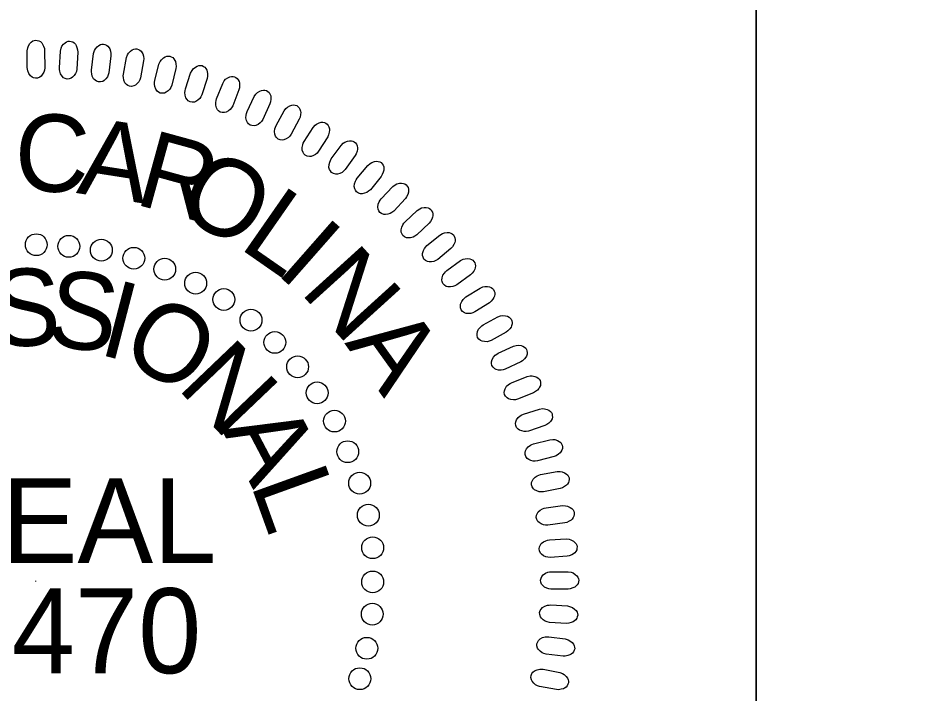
# Model space of a CAD drawing. Extents: x 505237 to 506921, y 424821 to 425921.
# Drawn here: x 506749.5 to 506815.5, y 425800.2 to 425849.7 of the extents above; entities that cross this region are included whole.
import ezdxf

# ---------------------------------------------------------------- set-up
doc = ezdxf.new("R2010")
doc.units = 0
doc.layers.add('Prop Horizontal Alignment Station Label', color=7, linetype='Continuous')
doc.layers.add('Sheet PE Seal Cell', color=7, linetype='Continuous')

msp = doc.modelspace()

# ---------------------------------------------------------------- linework, layer by layer
at = {"layer": 'Prop Horizontal Alignment Station Label'}
msp.add_line((506803.715, 425870.619), (506803.715, 425758.169), dxfattribs=at)
for points in [[(506703.665, 425870.619), (506803.715, 425870.619), (506803.715, 425758.119), (506703.665, 425758.119)], [(506803.715, 425870.619), (506903.715, 425870.619), (506903.715, 425758.119), (506803.715, 425758.119)]]:
    msp.add_lwpolyline(points, close=True, dxfattribs=at)
at = {"layer": 'Sheet PE Seal Cell'}
msp.add_line((506750.802, 425808.43), (506750.802, 425808.383), dxfattribs=at)
for points in [[(506750.198, 425846.115), (506750.198, 425847.342), (506750.236, 425847.561), (506750.289, 425847.702), (506750.4, 425847.871), (506750.498, 425847.981), (506750.61, 425848.061), (506750.714, 425848.1), (506750.827, 425848.12), (506750.938, 425848.1), (506751.058, 425848.071), (506751.163, 425848.011), (506751.267, 425847.911), (506751.327, 425847.831), (506751.394, 425847.681), (506751.455, 425847.502), (506751.477, 425847.342), (506751.484, 425846.086), (506751.462, 425845.916), (506751.417, 425845.777), (506751.327, 425845.617), (506751.215, 425845.477), (506751.118, 425845.398), (506750.961, 425845.338), (506750.812, 425845.318), (506750.662, 425845.358), (506750.558, 425845.407), (506750.43, 425845.507), (506750.311, 425845.677), (506750.243, 425845.856), (506750.214, 425845.986)], [(506752.558, 425846.09), (506752.635, 425847.314), (506752.685, 425847.531), (506752.747, 425847.667), (506752.869, 425847.829), (506752.973, 425847.932), (506753.09, 425848.005), (506753.197, 425848.038), (506753.31, 425848.051), (506753.421, 425848.024), (506753.538, 425847.987), (506753.639, 425847.92), (506753.737, 425847.815), (506753.792, 425847.731), (506753.85, 425847.578), (506753.898, 425847.395), (506753.911, 425847.234), (506753.839, 425845.979), (506753.806, 425845.811), (506753.752, 425845.675), (506753.653, 425845.522), (506753.532, 425845.389), (506753.43, 425845.315), (506753.27, 425845.266), (506753.119, 425845.255), (506752.973, 425845.304), (506752.871, 425845.361), (506752.751, 425845.468), (506752.642, 425845.645), (506752.586, 425845.828), (506752.565, 425845.96)], [(506754.92, 425845.916), (506755.074, 425847.133), (506755.138, 425847.346), (506755.208, 425847.477), (506755.34, 425847.632), (506755.451, 425847.729), (506755.572, 425847.793), (506755.68, 425847.82), (506755.794, 425847.826), (506755.903, 425847.791), (506756.018, 425847.747), (506756.114, 425847.675), (506756.205, 425847.562), (506756.255, 425847.476), (506756.304, 425847.319), (506756.34, 425847.133), (506756.342, 425846.972), (506756.192, 425845.725), (506756.148, 425845.559), (506756.087, 425845.427), (506755.978, 425845.279), (506755.849, 425845.155), (506755.743, 425845.088), (506755.579, 425845.048), (506755.428, 425845.047), (506755.285, 425845.105), (506755.187, 425845.168), (506755.073, 425845.283), (506754.976, 425845.466), (506754.932, 425845.653), (506754.919, 425845.785)], [(506757.26, 425845.63), (506757.49, 425846.835), (506757.567, 425847.043), (506757.645, 425847.17), (506757.787, 425847.316), (506757.903, 425847.405), (506758.028, 425847.463), (506758.138, 425847.482), (506758.252, 425847.481), (506758.358, 425847.441), (506758.47, 425847.389), (506758.562, 425847.31), (506758.646, 425847.193), (506758.69, 425847.104), (506758.728, 425846.944), (506758.753, 425846.756), (506758.745, 425846.595), (506758.517, 425845.359), (506758.463, 425845.197), (506758.393, 425845.068), (506758.275, 425844.928), (506758.138, 425844.812), (506758.028, 425844.752), (506757.863, 425844.723), (506757.712, 425844.731), (506757.573, 425844.798), (506757.48, 425844.867), (506757.374, 425844.989), (506757.288, 425845.178), (506757.255, 425845.366), (506757.25, 425845.5)], [(506759.565, 425845.157), (506759.87, 425846.345), (506759.961, 425846.548), (506760.046, 425846.671), (506760.197, 425846.807), (506760.318, 425846.889), (506760.447, 425846.938), (506760.558, 425846.951), (506760.672, 425846.943), (506760.775, 425846.895), (506760.884, 425846.836), (506760.97, 425846.753), (506761.046, 425846.63), (506761.085, 425846.538), (506761.113, 425846.376), (506761.126, 425846.187), (506761.109, 425846.027), (506760.803, 425844.808), (506760.739, 425844.65), (506760.66, 425844.526), (506760.534, 425844.393), (506760.391, 425844.286), (506760.277, 425844.233), (506760.11, 425844.214), (506759.96, 425844.232), (506759.826, 425844.308), (506759.737, 425844.382), (506759.638, 425844.51), (506759.564, 425844.704), (506759.544, 425844.895), (506759.547, 425845.027)], [(506761.815, 425844.535), (506762.194, 425845.702), (506762.298, 425845.9), (506762.391, 425846.016), (506762.55, 425846.143), (506762.676, 425846.217), (506762.807, 425846.258), (506762.919, 425846.264), (506763.032, 425846.248), (506763.132, 425846.194), (506763.237, 425846.129), (506763.318, 425846.039), (506763.386, 425845.913), (506763.419, 425845.818), (506763.437, 425845.655), (506763.438, 425845.466), (506763.41, 425845.307), (506763.029, 425844.11), (506762.955, 425843.955), (506762.869, 425843.836), (506762.735, 425843.712), (506762.585, 425843.614), (506762.468, 425843.568), (506762.3, 425843.56), (506762.151, 425843.588), (506762.022, 425843.671), (506761.938, 425843.751), (506761.848, 425843.885), (506761.786, 425844.083), (506761.778, 425844.275), (506761.79, 425844.408)], [(506764.099, 425843.801), (506764.55, 425844.942), (506764.666, 425845.132), (506764.766, 425845.243), (506764.933, 425845.359), (506765.064, 425845.425), (506765.197, 425845.458), (506765.309, 425845.457), (506765.421, 425845.434), (506765.517, 425845.374), (506765.618, 425845.302), (506765.693, 425845.208), (506765.754, 425845.077), (506765.78, 425844.981), (506765.787, 425844.817), (506765.777, 425844.628), (506765.739, 425844.471), (506765.283, 425843.3), (506765.2, 425843.151), (506765.107, 425843.037), (506764.965, 425842.923), (506764.809, 425842.833), (506764.69, 425842.795), (506764.521, 425842.798), (506764.375, 425842.834), (506764.251, 425842.926), (506764.172, 425843.011), (506764.09, 425843.15), (506764.042, 425843.352), (506764.045, 425843.544), (506764.065, 425843.675)], [(506766.34, 425842.868), (506766.863, 425843.978), (506766.99, 425844.16), (506767.097, 425844.265), (506767.27, 425844.37), (506767.405, 425844.428), (506767.54, 425844.452), (506767.652, 425844.444), (506767.762, 425844.414), (506767.855, 425844.348), (506767.951, 425844.271), (506768.02, 425844.172), (506768.072, 425844.037), (506768.092, 425843.94), (506768.089, 425843.775), (506768.067, 425843.588), (506768.02, 425843.433), (506767.491, 425842.293), (506767.399, 425842.15), (506767.298, 425842.042), (506767.149, 425841.936), (506766.988, 425841.858), (506766.866, 425841.827), (506766.699, 425841.839), (506766.555, 425841.885), (506766.437, 425841.985), (506766.364, 425842.074), (506766.291, 425842.219), (506766.255, 425842.423), (506766.27, 425842.614), (506766.299, 425842.744)], [(506768.465, 425841.854), (506769.055, 425842.928), (506769.194, 425843.102), (506769.307, 425843.2), (506769.487, 425843.294), (506769.625, 425843.344), (506769.762, 425843.359), (506769.873, 425843.344), (506769.981, 425843.308), (506770.069, 425843.236), (506770.159, 425843.152), (506770.222, 425843.049), (506770.266, 425842.912), (506770.28, 425842.813), (506770.268, 425842.649), (506770.233, 425842.463), (506770.176, 425842.313), (506769.577, 425841.208), (506769.476, 425841.07), (506769.369, 425840.969), (506769.214, 425840.873), (506769.048, 425840.804), (506768.925, 425840.781), (506768.758, 425840.804), (506768.617, 425840.859), (506768.505, 425840.966), (506768.438, 425841.06), (506768.375, 425841.209), (506768.352, 425841.415), (506768.379, 425841.604), (506768.415, 425841.733)], [(506770.523, 425840.669), (506771.18, 425841.705), (506771.33, 425841.87), (506771.448, 425841.96), (506771.634, 425842.043), (506771.775, 425842.084), (506771.912, 425842.091), (506772.022, 425842.068), (506772.128, 425842.025), (506772.212, 425841.948), (506772.296, 425841.859), (506772.353, 425841.752), (506772.388, 425841.612), (506772.395, 425841.513), (506772.372, 425841.35), (506772.326, 425841.166), (506772.26, 425841.02), (506771.593, 425839.955), (506771.483, 425839.824), (506771.37, 425839.73), (506771.209, 425839.643), (506771.04, 425839.585), (506770.915, 425839.57), (506770.75, 425839.603), (506770.613, 425839.667), (506770.509, 425839.78), (506770.447, 425839.879), (506770.392, 425840.031), (506770.383, 425840.238), (506770.422, 425840.426), (506770.467, 425840.552)], [(506772.523, 425839.397), (506773.244, 425840.389), (506773.404, 425840.545), (506773.528, 425840.627), (506773.718, 425840.698), (506773.861, 425840.73), (506773.999, 425840.729), (506774.107, 425840.699), (506774.21, 425840.649), (506774.289, 425840.568), (506774.368, 425840.473), (506774.417, 425840.363), (506774.443, 425840.221), (506774.445, 425840.121), (506774.412, 425839.96), (506774.354, 425839.78), (506774.279, 425839.638), (506773.546, 425838.617), (506773.428, 425838.493), (506773.31, 425838.406), (506773.144, 425838.33), (506772.971, 425838.282), (506772.845, 425838.275), (506772.683, 425838.319), (506772.55, 425838.391), (506772.453, 425838.511), (506772.398, 425838.613), (506772.353, 425838.768), (506772.356, 425838.976), (506772.407, 425839.161), (506772.459, 425839.283)], [(506774.418, 425837.981), (506775.2, 425838.926), (506775.369, 425839.071), (506775.498, 425839.146), (506775.693, 425839.205), (506775.837, 425839.228), (506775.975, 425839.217), (506776.081, 425839.182), (506776.18, 425839.125), (506776.254, 425839.039), (506776.327, 425838.939), (506776.369, 425838.826), (506776.386, 425838.683), (506776.382, 425838.583), (506776.337, 425838.425), (506776.27, 425838.249), (506776.186, 425838.111), (506775.39, 425837.139), (506775.265, 425837.022), (506775.141, 425836.943), (506774.97, 425836.877), (506774.795, 425836.841), (506774.669, 425836.841), (506774.51, 425836.895), (506774.382, 425836.976), (506774.292, 425837.102), (506774.243, 425837.207), (506774.209, 425837.364), (506774.225, 425837.571), (506774.288, 425837.753), (506774.348, 425837.871)], [(506776.19, 425836.467), (506777.031, 425837.362), (506777.208, 425837.496), (506777.341, 425837.562), (506777.539, 425837.609), (506777.685, 425837.623), (506777.821, 425837.604), (506777.925, 425837.562), (506778.021, 425837.499), (506778.089, 425837.408), (506778.155, 425837.304), (506778.191, 425837.189), (506778.199, 425837.045), (506778.188, 425836.945), (506778.134, 425836.79), (506778.055, 425836.619), (506777.962, 425836.487), (506777.107, 425835.566), (506776.975, 425835.458), (506776.847, 425835.387), (506776.672, 425835.332), (506776.495, 425835.306), (506776.369, 425835.315), (506776.214, 425835.379), (506776.091, 425835.466), (506776.01, 425835.598), (506775.968, 425835.706), (506775.943, 425835.865), (506775.972, 425836.071), (506776.046, 425836.248), (506776.113, 425836.363)], [(506777.935, 425834.775), (506778.83, 425835.614), (506779.015, 425835.737), (506779.153, 425835.795), (506779.353, 425835.829), (506779.499, 425835.833), (506779.634, 425835.806), (506779.735, 425835.757), (506779.827, 425835.689), (506779.889, 425835.594), (506779.949, 425835.486), (506779.977, 425835.369), (506779.976, 425835.224), (506779.958, 425835.126), (506779.896, 425834.975), (506779.806, 425834.808), (506779.705, 425834.682), (506778.793, 425833.817), (506778.655, 425833.717), (506778.522, 425833.654), (506778.345, 425833.611), (506778.166, 425833.597), (506778.041, 425833.613), (506777.89, 425833.686), (506777.773, 425833.782), (506777.7, 425833.918), (506777.665, 425834.028), (506777.65, 425834.189), (506777.692, 425834.392), (506777.777, 425834.565), (506777.851, 425834.675)], [(506779.548, 425833.029), (506780.493, 425833.811), (506780.686, 425833.922), (506780.827, 425833.971), (506781.029, 425833.992), (506781.176, 425833.987), (506781.309, 425833.952), (506781.406, 425833.896), (506781.493, 425833.823), (506781.549, 425833.724), (506781.602, 425833.612), (506781.623, 425833.493), (506781.613, 425833.349), (506781.589, 425833.252), (506781.517, 425833.105), (506781.417, 425832.945), (506781.308, 425832.826), (506780.344, 425832.019), (506780.2, 425831.928), (506780.063, 425831.874), (506779.883, 425831.842), (506779.704, 425831.839), (506779.581, 425831.863), (506779.434, 425831.945), (506779.324, 425832.048), (506779.26, 425832.189), (506779.231, 425832.301), (506779.227, 425832.462), (506779.281, 425832.663), (506779.377, 425832.829), (506779.458, 425832.935)], [(506781.009, 425831.207), (506782.001, 425831.928), (506782.201, 425832.026), (506782.344, 425832.066), (506782.548, 425832.075), (506782.693, 425832.061), (506782.824, 425832.017), (506782.918, 425831.956), (506783, 425831.877), (506783.05, 425831.774), (506783.095, 425831.66), (506783.109, 425831.541), (506783.089, 425831.397), (506783.06, 425831.302), (506782.978, 425831.159), (506782.869, 425831.006), (506782.753, 425830.894), (506781.74, 425830.149), (506781.59, 425830.068), (506781.45, 425830.022), (506781.269, 425830.001), (506781.09, 425830.009), (506780.968, 425830.041), (506780.828, 425830.133), (506780.723, 425830.242), (506780.668, 425830.386), (506780.647, 425830.5), (506780.653, 425830.662), (506780.72, 425830.858), (506780.825, 425831.018), (506780.913, 425831.119)], [(506782.41, 425829.261), (506783.446, 425829.919), (506783.651, 425830.005), (506783.797, 425830.036), (506784, 425830.032), (506784.145, 425830.008), (506784.272, 425829.957), (506784.362, 425829.889), (506784.439, 425829.806), (506784.482, 425829.7), (506784.521, 425829.583), (506784.527, 425829.463), (506784.498, 425829.321), (506784.463, 425829.227), (506784.373, 425829.09), (506784.253, 425828.944), (506784.131, 425828.84), (506783.074, 425828.16), (506782.919, 425828.088), (506782.777, 425828.051), (506782.594, 425828.041), (506782.416, 425828.061), (506782.296, 425828.1), (506782.162, 425828.201), (506782.065, 425828.317), (506782.019, 425828.464), (506782.005, 425828.579), (506782.021, 425828.74), (506782.099, 425828.932), (506782.215, 425829.085), (506782.309, 425829.179)], [(506783.672, 425827.212), (506784.747, 425827.803), (506784.957, 425827.875), (506785.104, 425827.898), (506785.307, 425827.881), (506785.45, 425827.849), (506785.574, 425827.788), (506785.659, 425827.715), (506785.731, 425827.627), (506785.767, 425827.519), (506785.799, 425827.4), (506785.797, 425827.28), (506785.76, 425827.14), (506785.719, 425827.049), (506785.62, 425826.918), (506785.491, 425826.779), (506785.363, 425826.683), (506784.265, 425826.071), (506784.105, 425826.009), (506783.961, 425825.981), (506783.779, 425825.983), (506783.603, 425826.014), (506783.485, 425826.06), (506783.357, 425826.169), (506783.268, 425826.29), (506783.231, 425826.44), (506783.224, 425826.556), (506783.25, 425826.716), (506783.341, 425826.902), (506783.466, 425827.048), (506783.566, 425827.137)], [(506784.78, 425825.129), (506785.89, 425825.652), (506786.104, 425825.711), (506786.253, 425825.724), (506786.454, 425825.694), (506786.594, 425825.652), (506786.715, 425825.585), (506786.795, 425825.508), (506786.861, 425825.414), (506786.891, 425825.304), (506786.914, 425825.183), (506786.905, 425825.064), (506786.859, 425824.926), (506786.813, 425824.838), (506786.706, 425824.713), (506786.568, 425824.583), (506786.434, 425824.495), (506785.3, 425823.953), (506785.137, 425823.902), (506784.991, 425823.882), (506784.81, 425823.896), (506784.635, 425823.938), (506784.521, 425823.991), (506784.4, 425824.108), (506784.319, 425824.235), (506784.291, 425824.387), (506784.292, 425824.503), (506784.328, 425824.661), (506784.431, 425824.841), (506784.564, 425824.979), (506784.669, 425825.06)], [(506785.76, 425822.968), (506786.901, 425823.42), (506787.118, 425823.466), (506787.267, 425823.469), (506787.466, 425823.427), (506787.604, 425823.377), (506787.719, 425823.302), (506787.795, 425823.219), (506787.855, 425823.122), (506787.877, 425823.011), (506787.894, 425822.888), (506787.877, 425822.77), (506787.822, 425822.635), (506787.771, 425822.55), (506787.656, 425822.432), (506787.511, 425822.311), (506787.371, 425822.232), (506786.205, 425821.762), (506786.04, 425821.72), (506785.893, 425821.711), (506785.712, 425821.735), (506785.541, 425821.788), (506785.43, 425821.849), (506785.317, 425821.973), (506785.244, 425822.105), (506785.226, 425822.258), (506785.234, 425822.374), (506785.279, 425822.529), (506785.393, 425822.702), (506785.535, 425822.831), (506785.645, 425822.906)], [(506786.634, 425820.654), (506787.802, 425821.033), (506788.022, 425821.066), (506788.171, 425821.06), (506788.367, 425821.005), (506788.501, 425820.947), (506788.612, 425820.864), (506788.682, 425820.778), (506788.735, 425820.677), (506788.751, 425820.564), (506788.76, 425820.441), (506788.735, 425820.323), (506788.672, 425820.193), (506788.616, 425820.111), (506788.493, 425820), (506788.342, 425819.888), (506788.197, 425819.817), (506787.004, 425819.422), (506786.836, 425819.391), (506786.689, 425819.391), (506786.51, 425819.427), (506786.342, 425819.49), (506786.236, 425819.558), (506786.13, 425819.689), (506786.066, 425819.825), (506786.057, 425819.98), (506786.072, 425820.094), (506786.128, 425820.246), (506786.252, 425820.412), (506786.402, 425820.532), (506786.516, 425820.6)], [(506787.38, 425818.482), (506788.568, 425818.786), (506788.79, 425818.805), (506788.938, 425818.789), (506789.131, 425818.723), (506789.261, 425818.656), (506789.366, 425818.567), (506789.431, 425818.476), (506789.478, 425818.372), (506789.487, 425818.258), (506789.487, 425818.135), (506789.456, 425818.019), (506789.385, 425817.893), (506789.323, 425817.815), (506789.194, 425817.713), (506789.035, 425817.61), (506788.886, 425817.548), (506787.671, 425817.229), (506787.501, 425817.209), (506787.355, 425817.217), (506787.178, 425817.264), (506787.015, 425817.338), (506786.913, 425817.412), (506786.817, 425817.549), (506786.76, 425817.69), (506786.762, 425817.844), (506786.784, 425817.958), (506786.849, 425818.106), (506786.983, 425818.264), (506787.141, 425818.373), (506787.259, 425818.435)], [(506787.891, 425816.227), (506789.096, 425816.457), (506789.318, 425816.461), (506789.465, 425816.437), (506789.653, 425816.358), (506789.778, 425816.283), (506789.879, 425816.188), (506789.937, 425816.093), (506789.978, 425815.986), (506789.979, 425815.873), (506789.971, 425815.749), (506789.933, 425815.636), (506789.854, 425815.514), (506789.788, 425815.44), (506789.653, 425815.346), (506789.487, 425815.254), (506789.335, 425815.202), (506788.102, 425814.959), (506787.931, 425814.949), (506787.786, 425814.967), (506787.613, 425815.026), (506787.454, 425815.109), (506787.358, 425815.189), (506787.269, 425815.333), (506787.222, 425815.476), (506787.233, 425815.63), (506787.262, 425815.742), (506787.336, 425815.886), (506787.481, 425816.035), (506787.645, 425816.135), (506787.766, 425816.188)], [(506788.29, 425813.788), (506789.507, 425813.942), (506789.729, 425813.932), (506789.874, 425813.898), (506790.057, 425813.808), (506790.178, 425813.726), (506790.271, 425813.625), (506790.324, 425813.526), (506790.357, 425813.417), (506790.351, 425813.303), (506790.337, 425813.18), (506790.291, 425813.069), (506790.205, 425812.953), (506790.133, 425812.884), (506789.993, 425812.798), (506789.822, 425812.716), (506789.667, 425812.674), (506788.421, 425812.509), (506788.25, 425812.51), (506788.106, 425812.537), (506787.937, 425812.606), (506787.784, 425812.7), (506787.693, 425812.786), (506787.613, 425812.934), (506787.575, 425813.081), (506787.596, 425813.234), (506787.633, 425813.344), (506787.715, 425813.482), (506787.868, 425813.622), (506788.038, 425813.711), (506788.163, 425813.757)], [(506788.534, 425811.424), (506789.758, 425811.5), (506789.979, 425811.477), (506790.122, 425811.434), (506790.299, 425811.332), (506790.414, 425811.242), (506790.5, 425811.135), (506790.547, 425811.034), (506790.574, 425810.923), (506790.561, 425810.81), (506790.539, 425810.688), (506790.486, 425810.58), (506790.393, 425810.47), (506790.317, 425810.405), (506790.172, 425810.328), (506789.996, 425810.257), (506789.839, 425810.225), (506788.585, 425810.139), (506788.414, 425810.15), (506788.272, 425810.187), (506788.107, 425810.266), (506787.961, 425810.369), (506787.875, 425810.461), (506787.805, 425810.614), (506787.776, 425810.762), (506787.807, 425810.913), (506787.85, 425811.021), (506787.941, 425811.154), (506788.103, 425811.284), (506788.278, 425811.363), (506788.405, 425811.4)], [(506788.684, 425809.094), (506789.911, 425809.093), (506790.13, 425809.056), (506790.27, 425809.004), (506790.439, 425808.891), (506790.549, 425808.795), (506790.629, 425808.682), (506790.668, 425808.578), (506790.688, 425808.465), (506790.668, 425808.353), (506790.639, 425808.234), (506790.579, 425808.129), (506790.479, 425808.024), (506790.399, 425807.965), (506790.249, 425807.897), (506790.07, 425807.837), (506789.911, 425807.815), (506788.654, 425807.807), (506788.485, 425807.83), (506788.345, 425807.875), (506788.185, 425807.965), (506788.046, 425808.077), (506787.966, 425808.174), (506787.906, 425808.331), (506787.886, 425808.48), (506787.926, 425808.63), (506787.976, 425808.734), (506788.075, 425808.862), (506788.245, 425808.981), (506788.425, 425809.049), (506788.554, 425809.079)], [(506788.652, 425806.653), (506789.876, 425806.576), (506790.092, 425806.524), (506790.228, 425806.464), (506790.391, 425806.341), (506790.494, 425806.237), (506790.567, 425806.121), (506790.6, 425806.014), (506790.613, 425805.9), (506790.586, 425805.79), (506790.549, 425805.672), (506790.482, 425805.571), (506790.376, 425805.474), (506790.293, 425805.419), (506790.139, 425805.361), (506789.956, 425805.313), (506789.795, 425805.3), (506788.541, 425805.372), (506788.373, 425805.405), (506788.237, 425805.459), (506788.083, 425805.557), (506787.951, 425805.679), (506787.877, 425805.78), (506787.827, 425805.941), (506787.817, 425806.092), (506787.866, 425806.238), (506787.922, 425806.339), (506788.03, 425806.46), (506788.206, 425806.568), (506788.39, 425806.625), (506788.521, 425806.646)], [(506788.485, 425804.313), (506789.703, 425804.159), (506789.916, 425804.094), (506790.048, 425804.025), (506790.203, 425803.893), (506790.299, 425803.783), (506790.364, 425803.661), (506790.39, 425803.553), (506790.396, 425803.438), (506790.362, 425803.33), (506790.317, 425803.215), (506790.245, 425803.119), (506790.133, 425803.028), (506790.047, 425802.978), (506789.889, 425802.93), (506789.704, 425802.894), (506789.543, 425802.891), (506788.295, 425803.041), (506788.129, 425803.085), (506787.997, 425803.147), (506787.85, 425803.256), (506787.725, 425803.384), (506787.658, 425803.491), (506787.619, 425803.654), (506787.618, 425803.805), (506787.676, 425803.948), (506787.739, 425804.046), (506787.853, 425804.16), (506788.036, 425804.256), (506788.223, 425804.301), (506788.355, 425804.314)], [(506788.09, 425801.926), (506789.294, 425801.695), (506789.503, 425801.618), (506789.631, 425801.541), (506789.776, 425801.399), (506789.866, 425801.282), (506789.923, 425801.157), (506789.942, 425801.047), (506789.941, 425800.933), (506789.901, 425800.827), (506789.849, 425800.715), (506789.77, 425800.623), (506789.652, 425800.54), (506789.563, 425800.495), (506789.404, 425800.457), (506789.216, 425800.432), (506789.055, 425800.44), (506787.82, 425800.668), (506787.657, 425800.722), (506787.528, 425800.792), (506787.389, 425800.911), (506787.272, 425801.047), (506787.212, 425801.157), (506787.183, 425801.323), (506787.191, 425801.473), (506787.259, 425801.612), (506787.327, 425801.706), (506787.448, 425801.812), (506787.638, 425801.898), (506787.827, 425801.93), (506787.959, 425801.935)]]:
    msp.add_lwpolyline(points, close=True, dxfattribs=at)
for centre in [(506750.86, 425833.099), (506753.249, 425832.979), (506755.637, 425832.701), (506758.026, 425832.103), (506760.295, 425831.306), (506762.565, 425830.271), (506764.635, 425829.075), (506766.626, 425827.562), (506768.377, 425825.928), (506770.05, 425824.136), (506771.483, 425822.223), (506772.757, 425820.152), (506773.73, 425817.903), (506774.606, 425815.592), (506775.243, 425813.242), (506775.561, 425810.852), (506775.561, 425808.342), (506775.532, 425805.978), (506775.134, 425803.469), (506774.617, 425801.238)]:
    msp.add_circle(centre, 0.801, dxfattribs=at)

# ---------------------------------------------------------------- texts
for s, height, rotation, p in [('C', 5.669, 357.60632, (506749.176, 425837.11)), ('A', 5.669, 351.11696, (506753.752, 425836.903)), ('R', 5.669, 344.6276, (506757.958, 425836.11)), ('O', 5.669, 331.64889, (506760.914, 425835.457)), ('L', 5.669, 325.15953, (506765.647, 425832.927)), ('I', 5.669, 318.67017, (506768.341, 425831.075)), ('N', 5.669, 312.18082, (506770.146, 425829.656)), ('S', 5.669, 1.30767, (506747.639, 425825.616)), ('S', 5.669, 353.36787, (506751.499, 425825.719)), ('I', 5.669, 345.42807, (506755.3, 425825.089)), ('O', 5.669, 329.54848, (506756.804, 425824.917)), ('A', 5.669, 305.69146, (506773.468, 425825.877)), ('N', 5.669, 313.66889, (506761.116, 425822.614)), ('A', 5.669, 297.78929, (506764.454, 425819.535)), ('L', 5.669, 289.84949, (506766.579, 425815.541)), ('SEAL', 6.2363, 360, (506742.76, 425809.721)), ('29470', 6.2363, 360, (506739.791, 425801.641))]:
    msp.add_text(s, height=height, rotation=rotation, dxfattribs=at).set_placement(p)

doc.saveas('drawing.dxf')
